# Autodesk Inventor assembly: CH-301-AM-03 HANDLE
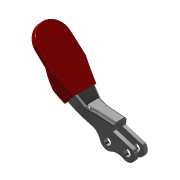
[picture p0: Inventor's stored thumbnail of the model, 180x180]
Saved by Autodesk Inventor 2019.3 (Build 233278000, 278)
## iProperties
Created: 2012-09
Part Number: CH-301-AM-03 HANDLE
Material: Ogólny
Document SubType Name: Assembly
Designer: CADENGINEERING4
Author: CADENGINEERING4
Revision Number: ÈÎºÎ
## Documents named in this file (3)
- D:\Vault_2016\Projekty\STRONA\Push-pull clamp\CH-301-AM\CH-301-AM-03 HANDLE.iam
- D:\Vault_2016\Projekty\STRONA\Push-pull clamp\CH-301-AM\CH-301-03-01.ipt
- D:\Vault_2016\Projekty\STRONA\Push-pull clamp\CH-301-AM\CH-301-03-02.ipt
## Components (2 placed, 2 different names)
1. CH-301-03-01_11
2. CH-301-03-02_12
